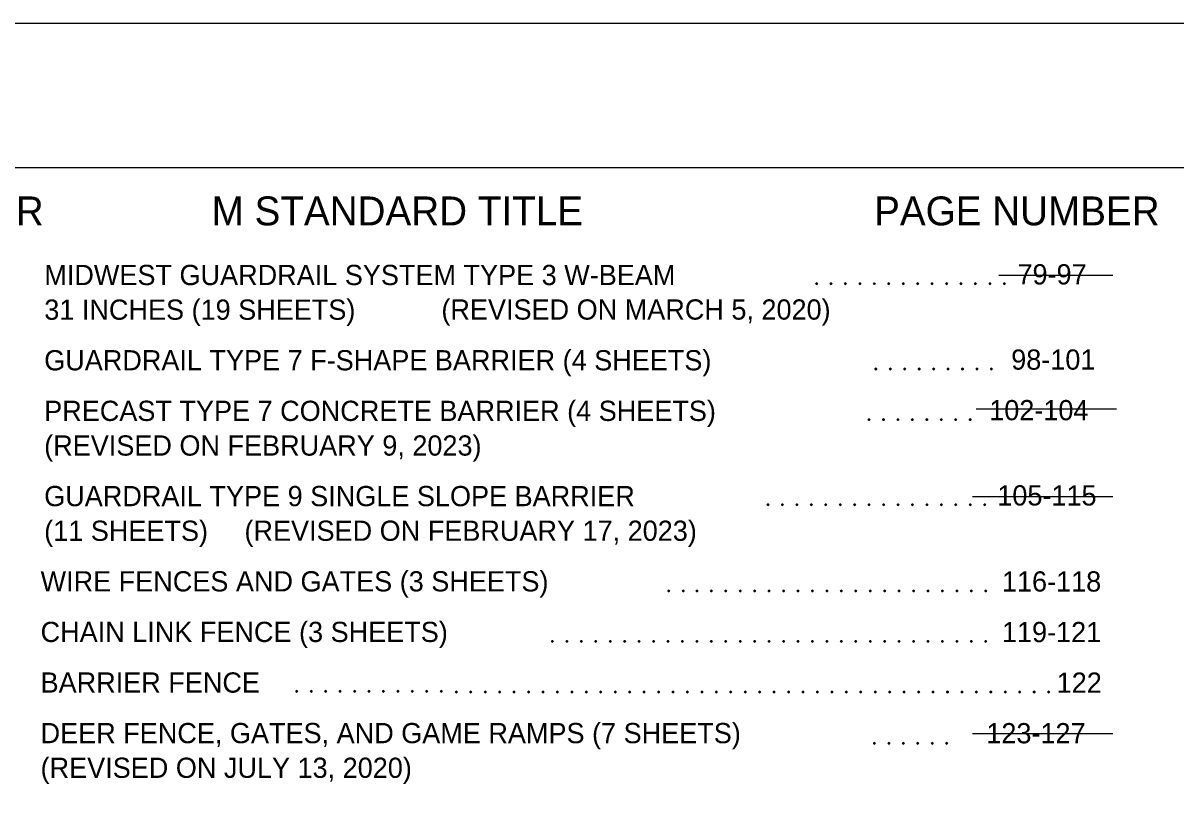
# Model space of a CAD drawing. Extents: x 0 to 1.42, y 0 to 0.92.
# Drawn here: x 0.6093 to 0.9418, y 0.6937 to 0.9167 of the extents above; entities that cross this region are included whole.
import ezdxf

# ---------------------------------------------------------------- set-up
doc = ezdxf.new("R2010")
doc.units = 0
for name, color, linetype in [('DRAFT_Text-Notes', 7, 'Continuous'), ('DRAFT_Text-Titles', 7, 'Continuous'), ('SHEET_Lines', 7, 'Continuous'), ('SHEET_Plot Boundary', 7, 'Continuous')]:
    doc.layers.add(name, color=color, linetype=linetype)

msp = doc.modelspace()

# ---------------------------------------------------------------- linework, layer by layer
at = {"layer": 'DRAFT_Text-Notes'}
for centre in [(0.83814, 0.84148), (0.84231, 0.84148), (0.84648, 0.84148), (0.85064, 0.84148), (0.85481, 0.84148), (0.85898, 0.84148), (0.86314, 0.84148), (0.86731, 0.84148), (0.87148, 0.84148), (0.87564, 0.84148), (0.87981, 0.84148), (0.88398, 0.84148), (0.88814, 0.84148), (0.89231, 0.84148), (0.85525, 0.81689), (0.85942, 0.81689), (0.86359, 0.81689), (0.86775, 0.81689), (0.87192, 0.81689), (0.87609, 0.81689), (0.88025, 0.81689), (0.88442, 0.81689), (0.88859, 0.81689), (0.85329, 0.8023), (0.85746, 0.8023), (0.86162, 0.8023), (0.86579, 0.8023), (0.86996, 0.8023), (0.87412, 0.8023), (0.87829, 0.8023), (0.88246, 0.8023), (0.82416, 0.7777), (0.82832, 0.7777), (0.83249, 0.7777), (0.83666, 0.7777), (0.84082, 0.7777), (0.84499, 0.7777), (0.84916, 0.7777), (0.85332, 0.7777), (0.85749, 0.7777), (0.86166, 0.7777), (0.86582, 0.7777), (0.86999, 0.7777), (0.87416, 0.7777), (0.87832, 0.7777), (0.88249, 0.7777), (0.88666, 0.7777), (0.79553, 0.75288), (0.79969, 0.75288), (0.80363, 0.75288), (0.8078, 0.75288), (0.81197, 0.75288), (0.81613, 0.75288), (0.8203, 0.75288), (0.82447, 0.75288), (0.82863, 0.75288), (0.8328, 0.75288), (0.83697, 0.75288), (0.84113, 0.75288), (0.8453, 0.75288), (0.84947, 0.75288), (0.85363, 0.75288), (0.8578, 0.75288), (0.86197, 0.75288), (0.86613, 0.75288), (0.8703, 0.75288), (0.87447, 0.75288), (0.87863, 0.75288), (0.8828, 0.75288), (0.88697, 0.75288), (0.76197, 0.73829), (0.76613, 0.73829), (0.7703, 0.73829), (0.77447, 0.73829), (0.77863, 0.73829), (0.7828, 0.73829), (0.78697, 0.73829), (0.79113, 0.73829), (0.7953, 0.73829), (0.79947, 0.73829), (0.80363, 0.73829), (0.8078, 0.73829), (0.81197, 0.73829), (0.81613, 0.73829), (0.8203, 0.73829), (0.82447, 0.73829), (0.82863, 0.73829), (0.8328, 0.73829), (0.83697, 0.73829), (0.84113, 0.73829), (0.8453, 0.73829), (0.84947, 0.73829), (0.85363, 0.73829), (0.8578, 0.73829), (0.86197, 0.73829), (0.86613, 0.73829), (0.8703, 0.73829), (0.87447, 0.73829), (0.87863, 0.73829), (0.8828, 0.73829), (0.88697, 0.73829), (0.68821, 0.7239), (0.69238, 0.7239), (0.69654, 0.7239), (0.70071, 0.7239), (0.70488, 0.7239), (0.70904, 0.7239), (0.71321, 0.7239), (0.71738, 0.7239), (0.72154, 0.7239), (0.72571, 0.7239), (0.72988, 0.7239), (0.73425, 0.7237), (0.73842, 0.7237), (0.74259, 0.7237), (0.74675, 0.7237), (0.75092, 0.7237), (0.75509, 0.7237), (0.75925, 0.7237), (0.76342, 0.7237), (0.76759, 0.7237), (0.77175, 0.7237), (0.77592, 0.7237), (0.78009, 0.7237), (0.78425, 0.7237), (0.78842, 0.7237), (0.79259, 0.7237), (0.79675, 0.7237), (0.80092, 0.7237), (0.80509, 0.7237), (0.80925, 0.7237), (0.81342, 0.7237), (0.81759, 0.7237), (0.82175, 0.7237), (0.82592, 0.7237), (0.83009, 0.7237), (0.83425, 0.7237), (0.83842, 0.7237), (0.84259, 0.7237), (0.84675, 0.7237), (0.85092, 0.7237), (0.85509, 0.7237), (0.85925, 0.7237), (0.86342, 0.7237), (0.86759, 0.7237), (0.87175, 0.7237), (0.87592, 0.7237), (0.88009, 0.7237), (0.88425, 0.7237), (0.88842, 0.7237), (0.89259, 0.7237), (0.89675, 0.7237), (0.90092, 0.7237), (0.90509, 0.7237), (0.85486, 0.7089), (0.85902, 0.7089), (0.86319, 0.7089), (0.86736, 0.7089), (0.87152, 0.7089), (0.87569, 0.7089)]:
    msp.add_circle(centre, 0.000208, dxfattribs=at)
for centre, start, end in [((0.83814, 0.84148), 0, 180), ((0.83814, 0.84148), 180, 0), ((0.84231, 0.84148), 0, 180), ((0.84231, 0.84148), 180, 0), ((0.84648, 0.84148), 0, 180), ((0.84648, 0.84148), 180, 0), ((0.85064, 0.84148), 0, 180), ((0.85064, 0.84148), 180, 0), ((0.85898, 0.84148), 0, 180), ((0.85898, 0.84148), 180, 0), ((0.86314, 0.84148), 0, 180), ((0.86314, 0.84148), 180, 0), ((0.86731, 0.84148), 0, 180), ((0.86731, 0.84148), 180, 0), ((0.87148, 0.84148), 0, 180), ((0.87148, 0.84148), 180, 0), ((0.87564, 0.84148), 0, 180), ((0.87564, 0.84148), 180, 0), ((0.87981, 0.84148), 0, 180), ((0.87981, 0.84148), 180, 0), ((0.88398, 0.84148), 0, 180), ((0.88398, 0.84148), 180, 0), ((0.88814, 0.84148), 0, 180), ((0.88814, 0.84148), 180, 0), ((0.89231, 0.84148), 0, 180), ((0.89231, 0.84148), 180, 0), ((0.85525, 0.81689), 0, 180), ((0.85525, 0.81689), 180, 0), ((0.85942, 0.81689), 0, 180), ((0.85942, 0.81689), 180, 0), ((0.86359, 0.81689), 0, 180), ((0.86359, 0.81689), 180, 0), ((0.86775, 0.81689), 0, 180), ((0.86775, 0.81689), 180, 0), ((0.87192, 0.81689), 0, 180), ((0.87192, 0.81689), 180, 0), ((0.87609, 0.81689), 0, 180), ((0.87609, 0.81689), 180, 0), ((0.88025, 0.81689), 0, 180), ((0.88025, 0.81689), 180, 0), ((0.88442, 0.81689), 0, 180), ((0.88442, 0.81689), 180, 0), ((0.88859, 0.81689), 0, 180), ((0.88859, 0.81689), 180, 0), ((0.85329, 0.8023), 0, 180), ((0.85329, 0.8023), 180, 0), ((0.85746, 0.8023), 0, 180), ((0.85746, 0.8023), 180, 0), ((0.86162, 0.8023), 0, 180), ((0.86162, 0.8023), 180, 0), ((0.86579, 0.8023), 0, 180), ((0.86579, 0.8023), 180, 0), ((0.86996, 0.8023), 0, 180), ((0.86996, 0.8023), 180, 0), ((0.87412, 0.8023), 0, 180), ((0.87412, 0.8023), 180, 0), ((0.87829, 0.8023), 0, 180), ((0.87829, 0.8023), 180, 0), ((0.88246, 0.8023), 0, 180), ((0.88246, 0.8023), 180, 0), ((0.82416, 0.7777), 0, 180), ((0.82416, 0.7777), 180, 0), ((0.82832, 0.7777), 0, 180), ((0.82832, 0.7777), 180, 0), ((0.83249, 0.7777), 0, 180), ((0.83249, 0.7777), 180, 0), ((0.83666, 0.7777), 0, 180), ((0.83666, 0.7777), 180, 0), ((0.84082, 0.7777), 0, 180), ((0.84082, 0.7777), 180, 0), ((0.84499, 0.7777), 0, 180), ((0.84499, 0.7777), 180, 0), ((0.84916, 0.7777), 0, 180), ((0.84916, 0.7777), 180, 0), ((0.85332, 0.7777), 0, 180), ((0.85332, 0.7777), 180, 0), ((0.85749, 0.7777), 0, 180), ((0.85749, 0.7777), 180, 0), ((0.86166, 0.7777), 0, 180), ((0.86166, 0.7777), 180, 0), ((0.86582, 0.7777), 0, 180), ((0.86582, 0.7777), 180, 0), ((0.86999, 0.7777), 0, 180), ((0.86999, 0.7777), 180, 0), ((0.87416, 0.7777), 0, 180), ((0.87416, 0.7777), 180, 0), ((0.87832, 0.7777), 0, 180), ((0.87832, 0.7777), 180, 0), ((0.88249, 0.7777), 0, 180), ((0.88249, 0.7777), 180, 0), ((0.88666, 0.7777), 0, 180), ((0.88666, 0.7777), 180, 0), ((0.79553, 0.75288), 0, 180), ((0.79553, 0.75288), 180, 0), ((0.79969, 0.75288), 0, 180), ((0.79969, 0.75288), 180, 0), ((0.80363, 0.75288), 0, 180), ((0.80363, 0.75288), 180, 0), ((0.8078, 0.75288), 0, 180), ((0.8078, 0.75288), 180, 0), ((0.81197, 0.75288), 0, 180), ((0.81197, 0.75288), 180, 0), ((0.81613, 0.75288), 0, 180), ((0.81613, 0.75288), 180, 0), ((0.8203, 0.75288), 0, 180), ((0.8203, 0.75288), 180, 0), ((0.82447, 0.75288), 0, 180), ((0.82447, 0.75288), 180, 0), ((0.82863, 0.75288), 0, 180), ((0.82863, 0.75288), 180, 0), ((0.8328, 0.75288), 0, 180), ((0.8328, 0.75288), 180, 0), ((0.83697, 0.75288), 0, 180), ((0.83697, 0.75288), 180, 0), ((0.84113, 0.75288), 0, 180), ((0.84113, 0.75288), 180, 0), ((0.8453, 0.75288), 0, 180), ((0.8453, 0.75288), 180, 0), ((0.84947, 0.75288), 0, 180), ((0.84947, 0.75288), 180, 0), ((0.85363, 0.75288), 0, 180), ((0.85363, 0.75288), 180, 0), ((0.8578, 0.75288), 0, 180), ((0.8578, 0.75288), 180, 0), ((0.86197, 0.75288), 0, 180), ((0.86197, 0.75288), 180, 0), ((0.86613, 0.75288), 0, 180), ((0.86613, 0.75288), 180, 0), ((0.8703, 0.75288), 0, 180), ((0.8703, 0.75288), 180, 0), ((0.87447, 0.75288), 0, 180), ((0.87447, 0.75288), 180, 0), ((0.87863, 0.75288), 0, 180), ((0.87863, 0.75288), 180, 0), ((0.8828, 0.75288), 0, 180), ((0.8828, 0.75288), 180, 0), ((0.88697, 0.75288), 0, 180), ((0.88697, 0.75288), 180, 0), ((0.76197, 0.73829), 0, 180), ((0.76197, 0.73829), 180, 0), ((0.76613, 0.73829), 0, 180), ((0.76613, 0.73829), 180, 0), ((0.7703, 0.73829), 0, 180), ((0.7703, 0.73829), 180, 0), ((0.77447, 0.73829), 0, 180), ((0.77447, 0.73829), 180, 0), ((0.77863, 0.73829), 0, 180), ((0.77863, 0.73829), 180, 0), ((0.7828, 0.73829), 0, 180), ((0.7828, 0.73829), 180, 0), ((0.78697, 0.73829), 0, 180), ((0.78697, 0.73829), 180, 0), ((0.79113, 0.73829), 0, 180), ((0.79113, 0.73829), 180, 0), ((0.7953, 0.73829), 0, 180), ((0.7953, 0.73829), 180, 0), ((0.79947, 0.73829), 0, 180), ((0.79947, 0.73829), 180, 0), ((0.80363, 0.73829), 0, 180), ((0.80363, 0.73829), 180, 0), ((0.8078, 0.73829), 0, 180), ((0.8078, 0.73829), 180, 0), ((0.81197, 0.73829), 0, 180), ((0.81197, 0.73829), 180, 0), ((0.81613, 0.73829), 0, 180), ((0.81613, 0.73829), 180, 0), ((0.8203, 0.73829), 0, 180), ((0.8203, 0.73829), 180, 0), ((0.82447, 0.73829), 0, 180), ((0.82447, 0.73829), 180, 0), ((0.82863, 0.73829), 0, 180), ((0.82863, 0.73829), 180, 0), ((0.8328, 0.73829), 0, 180), ((0.8328, 0.73829), 180, 0), ((0.83697, 0.73829), 0, 180), ((0.83697, 0.73829), 180, 0), ((0.84113, 0.73829), 0, 180), ((0.84113, 0.73829), 180, 0), ((0.8453, 0.73829), 0, 180), ((0.8453, 0.73829), 180, 0), ((0.84947, 0.73829), 0, 180), ((0.84947, 0.73829), 180, 0), ((0.85363, 0.73829), 0, 180), ((0.85363, 0.73829), 180, 0), ((0.8578, 0.73829), 0, 180), ((0.8578, 0.73829), 180, 0), ((0.86197, 0.73829), 0, 180), ((0.86197, 0.73829), 180, 0), ((0.86613, 0.73829), 0, 180), ((0.86613, 0.73829), 180, 0), ((0.8703, 0.73829), 0, 180), ((0.8703, 0.73829), 180, 0), ((0.87447, 0.73829), 0, 180), ((0.87447, 0.73829), 180, 0), ((0.87863, 0.73829), 0, 180), ((0.87863, 0.73829), 180, 0), ((0.8828, 0.73829), 0, 180), ((0.8828, 0.73829), 180, 0), ((0.88697, 0.73829), 0, 180), ((0.88697, 0.73829), 180, 0), ((0.68821, 0.7239), 0, 180), ((0.68821, 0.7239), 180, 0), ((0.69238, 0.7239), 0, 180), ((0.69238, 0.7239), 180, 0), ((0.69654, 0.7239), 0, 180), ((0.69654, 0.7239), 180, 0), ((0.70071, 0.7239), 0, 180), ((0.70071, 0.7239), 180, 0), ((0.70488, 0.7239), 0, 180), ((0.70488, 0.7239), 180, 0), ((0.70904, 0.7239), 0, 180), ((0.70904, 0.7239), 180, 0), ((0.71321, 0.7239), 0, 180), ((0.71321, 0.7239), 180, 0), ((0.71738, 0.7239), 0, 180), ((0.71738, 0.7239), 180, 0), ((0.72154, 0.7239), 0, 180), ((0.72154, 0.7239), 180, 0), ((0.72571, 0.7239), 0, 180), ((0.72571, 0.7239), 180, 0), ((0.72988, 0.7239), 0, 180), ((0.72988, 0.7239), 180, 0), ((0.73425, 0.7237), 0, 180), ((0.73425, 0.7237), 180, 0), ((0.73842, 0.7237), 0, 180), ((0.73842, 0.7237), 180, 0), ((0.74259, 0.7237), 0, 180), ((0.74259, 0.7237), 180, 0), ((0.74675, 0.7237), 0, 180), ((0.74675, 0.7237), 180, 0), ((0.75092, 0.7237), 0, 180), ((0.75092, 0.7237), 180, 0), ((0.75509, 0.7237), 0, 180), ((0.75509, 0.7237), 180, 0), ((0.75925, 0.7237), 0, 180), ((0.75925, 0.7237), 180, 0), ((0.76342, 0.7237), 0, 180), ((0.76342, 0.7237), 180, 0), ((0.76759, 0.7237), 0, 180), ((0.76759, 0.7237), 180, 0), ((0.77175, 0.7237), 0, 180), ((0.77175, 0.7237), 180, 0), ((0.77592, 0.7237), 0, 180), ((0.77592, 0.7237), 180, 0), ((0.78009, 0.7237), 0, 180), ((0.78009, 0.7237), 180, 0), ((0.78425, 0.7237), 0, 180), ((0.78425, 0.7237), 180, 0), ((0.78842, 0.7237), 0, 180), ((0.78842, 0.7237), 180, 0), ((0.79259, 0.7237), 0, 180), ((0.79259, 0.7237), 180, 0), ((0.79675, 0.7237), 0, 180), ((0.79675, 0.7237), 180, 0), ((0.80092, 0.7237), 0, 180), ((0.80092, 0.7237), 180, 0), ((0.80509, 0.7237), 0, 180), ((0.80509, 0.7237), 180, 0), ((0.80925, 0.7237), 0, 180), ((0.80925, 0.7237), 180, 0), ((0.81342, 0.7237), 0, 180), ((0.81342, 0.7237), 180, 0), ((0.81759, 0.7237), 0, 180), ((0.81759, 0.7237), 180, 0), ((0.82175, 0.7237), 0, 180), ((0.82175, 0.7237), 180, 0), ((0.82592, 0.7237), 0, 180), ((0.82592, 0.7237), 180, 0), ((0.83009, 0.7237), 0, 180), ((0.83009, 0.7237), 180, 0), ((0.83425, 0.7237), 0, 180), ((0.83425, 0.7237), 180, 0), ((0.83842, 0.7237), 0, 180), ((0.83842, 0.7237), 180, 0), ((0.84259, 0.7237), 0, 180), ((0.84259, 0.7237), 180, 0), ((0.84675, 0.7237), 0, 180), ((0.84675, 0.7237), 180, 0), ((0.85092, 0.7237), 0, 180), ((0.85092, 0.7237), 180, 0), ((0.85509, 0.7237), 0, 180), ((0.85509, 0.7237), 180, 0), ((0.85925, 0.7237), 0, 180), ((0.85925, 0.7237), 180, 0), ((0.86342, 0.7237), 0, 180), ((0.86342, 0.7237), 180, 0), ((0.86759, 0.7237), 0, 180), ((0.86759, 0.7237), 180, 0), ((0.87175, 0.7237), 0, 180), ((0.87175, 0.7237), 180, 0), ((0.87592, 0.7237), 0, 180), ((0.87592, 0.7237), 180, 0), ((0.88009, 0.7237), 0, 180), ((0.88009, 0.7237), 180, 0), ((0.88425, 0.7237), 0, 180), ((0.88425, 0.7237), 180, 0), ((0.88842, 0.7237), 0, 180), ((0.88842, 0.7237), 180, 0), ((0.89259, 0.7237), 0, 180), ((0.89259, 0.7237), 180, 0), ((0.89675, 0.7237), 0, 180), ((0.89675, 0.7237), 180, 0), ((0.90092, 0.7237), 0, 180), ((0.90092, 0.7237), 180, 0), ((0.90509, 0.7237), 0, 180), ((0.90509, 0.7237), 180, 0), ((0.85486, 0.7089), 0, 180), ((0.85486, 0.7089), 180, 0), ((0.85902, 0.7089), 0, 180), ((0.85902, 0.7089), 180, 0), ((0.86319, 0.7089), 0, 180), ((0.86319, 0.7089), 180, 0), ((0.86736, 0.7089), 0, 180), ((0.86736, 0.7089), 180, 0), ((0.87152, 0.7089), 0, 180), ((0.87152, 0.7089), 180, 0), ((0.87569, 0.7089), 0, 180), ((0.87569, 0.7089), 180, 0)]:
    msp.add_arc(centre, 0.000208, start, end, dxfattribs=at)
at = {"layer": 'DRAFT_Text-Titles'}
for p, q in [((0.89072, 0.84391), (0.92357, 0.84391)), ((0.88421, 0.80541), (0.92465, 0.80541)), ((0.88318, 0.7801), (0.92362, 0.7801)), ((0.88318, 0.71177), (0.92362, 0.71177))]:
    msp.add_line(p, q, dxfattribs=at)
at = {"layer": 'SHEET_Lines'}
msp.add_lwpolyline([(0.08333, 0.875), (1.375, 0.875), (1.375, 0.125), (0.08333, 0.125)], close=True, dxfattribs=at)
at = {"layer": 'SHEET_Plot Boundary'}
msp.add_lwpolyline([(0, 0.91667), (1.41667, 0.91667), (1.41667, 0), (0, 0)], close=True, dxfattribs=at)

# ---------------------------------------------------------------- texts
at = {"layer": 'DRAFT_Text-Notes'}
for s, height, p in [('MIDWEST GUARDRAIL SYSTEM TYPE 3 W-BEAM', 0.0058333, (0.6154, 0.84108)), ('79-97', 0.005833, (0.89611, 0.84127)), ('31 INCHES (19 SHEETS)', 0.0058333, (0.6154, 0.83108)), ('GUARDRAIL TYPE 7 F-SHAPE BARRIER (4 SHEETS)', 0.0058333, (0.61537, 0.81648)), ('98-101', 0.005833, (0.8943, 0.81668)), ('PRECAST TYPE 7 CONCRETE BARRIER (4 SHEETS)', 0.0058333, (0.61537, 0.80189)), ('102-104', 0.005833, (0.88796, 0.80209)), ('GUARDRAIL TYPE 9 SINGLE SLOPE BARRIER', 0.0058333, (0.61537, 0.7773)), ('105-115', 0.005833, (0.89029, 0.7775)), ('(11 SHEETS)', 0.0058333, (0.61537, 0.7673)), ('WIRE FENCES AND GATES (3 SHEETS)', 0.0058333, (0.61433, 0.75271)), ('116-118', 0.005833, (0.89163, 0.75267)), ('CHAIN LINK FENCE (3 SHEETS)', 0.0058333, (0.61433, 0.73812)), ('119-121', 0.005833, (0.89163, 0.73808)), ('BARRIER FENCE', 0.0058333, (0.61433, 0.72352)), ('122', 0.005833, (0.90742, 0.72349)), ('DEER FENCE, GATES, AND GAME RAMPS (7 SHEETS)', 0.0058333, (0.61433, 0.70893)), ('123-127', 0.005833, (0.88712, 0.7089))]:
    msp.add_text(s, height=height, dxfattribs=at).set_placement(p)
at = {"layer": 'DRAFT_Text-Titles'}
for s, height, p in [('PLAN NUMBER', 0.0083333, (0.53473, 0.85831)), ('M STANDARD TITLE', 0.0083333, (0.66367, 0.85831)), ('PAGE NUMBER', 0.0083333, (0.85476, 0.85831)), ('(REVISED ON MARCH 5, 2020)', 0.0058333, (0.72994, 0.83112)), ('(REVISED ON FEBRUARY 9, 2023)', 0.0058333, (0.61537, 0.79189)), ('(REVISED ON FEBRUARY 17, 2023)', 0.0058333, (0.67313, 0.76731)), ('(REVISED ON JULY 13, 2020)', 0.0058333, (0.61433, 0.69893))]:
    msp.add_text(s, height=height, dxfattribs=at).set_placement(p)

doc.saveas('drawing.dxf')
